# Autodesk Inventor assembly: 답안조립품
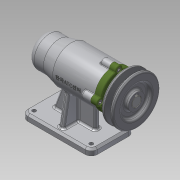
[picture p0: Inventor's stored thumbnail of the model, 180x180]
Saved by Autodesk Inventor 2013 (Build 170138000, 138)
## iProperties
Created: 2019-07
Part Number: 답안조립품
Document SubType Name: Assembly
Designer: Administrator
Author: Administrator
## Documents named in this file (12)
- C:\Users\Administrator\Desktop\490704V1036\답안조립품.iam
- C:\Users\Administrator\Desktop\490704V1036\본체.ipt
- C:\Users\Administrator\Desktop\490704V1036\V벨트풀리.ipt
- C:\Users\Administrator\Desktop\490704V1036\멈춤나사 M3.ipt
- C:\Users\Administrator\Desktop\490704V1036\베어링 6004.ipt
- C:\Users\Administrator\Desktop\490704V1036\베어링 51202.ipt
- C:\Users\Administrator\Desktop\490704V1036\볼트 M4.ipt
- C:\Users\Administrator\Desktop\490704V1036\어댑터슬리브.ipt
- C:\Users\Administrator\Desktop\490704V1036\오일 실.ipt
- C:\Users\Administrator\Desktop\490704V1036\축.ipt
- C:\Users\Administrator\Desktop\490704V1036\커버.ipt
- C:\Users\Administrator\Desktop\490704V1036\키 5 x 5 x 16.ipt
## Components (1 placed, 1 different names)
1. V벨트풀리:1
